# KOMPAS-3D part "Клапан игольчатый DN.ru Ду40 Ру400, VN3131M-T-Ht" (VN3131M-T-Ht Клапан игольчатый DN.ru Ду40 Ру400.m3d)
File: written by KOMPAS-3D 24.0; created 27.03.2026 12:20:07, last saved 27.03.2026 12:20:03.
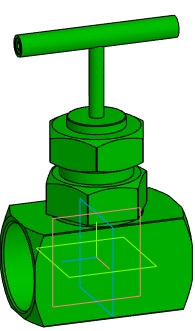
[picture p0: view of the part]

Document properties: Автор: Илья; Полное имя файла: D:\Обмен\Заказы с фриланса\DN.ru\VNxxM-T-Ht Клапан игольчатый DN.ru Ду8-50 Ру400\VN3131M-T-Ht Клапан игольчатый DN.ru Ду8-50 Ру400\DN40\VN3131M-T-Ht Клапан игольчатый DN.ru Ду40 Ру400.m3d

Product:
- Body: Body4  | qty 1
    Масса: 2.135076
- Part/product: Клапан игольчатый DN.ru Ду40 Ру400  | designation VN3131M-T-Ht
    Масса: 2
    Раздел спецификации: Прочие изделия
    Примечание: D090-02135

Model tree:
1. Body4  (labels: Body4)

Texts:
  VN3131M-T-Ht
